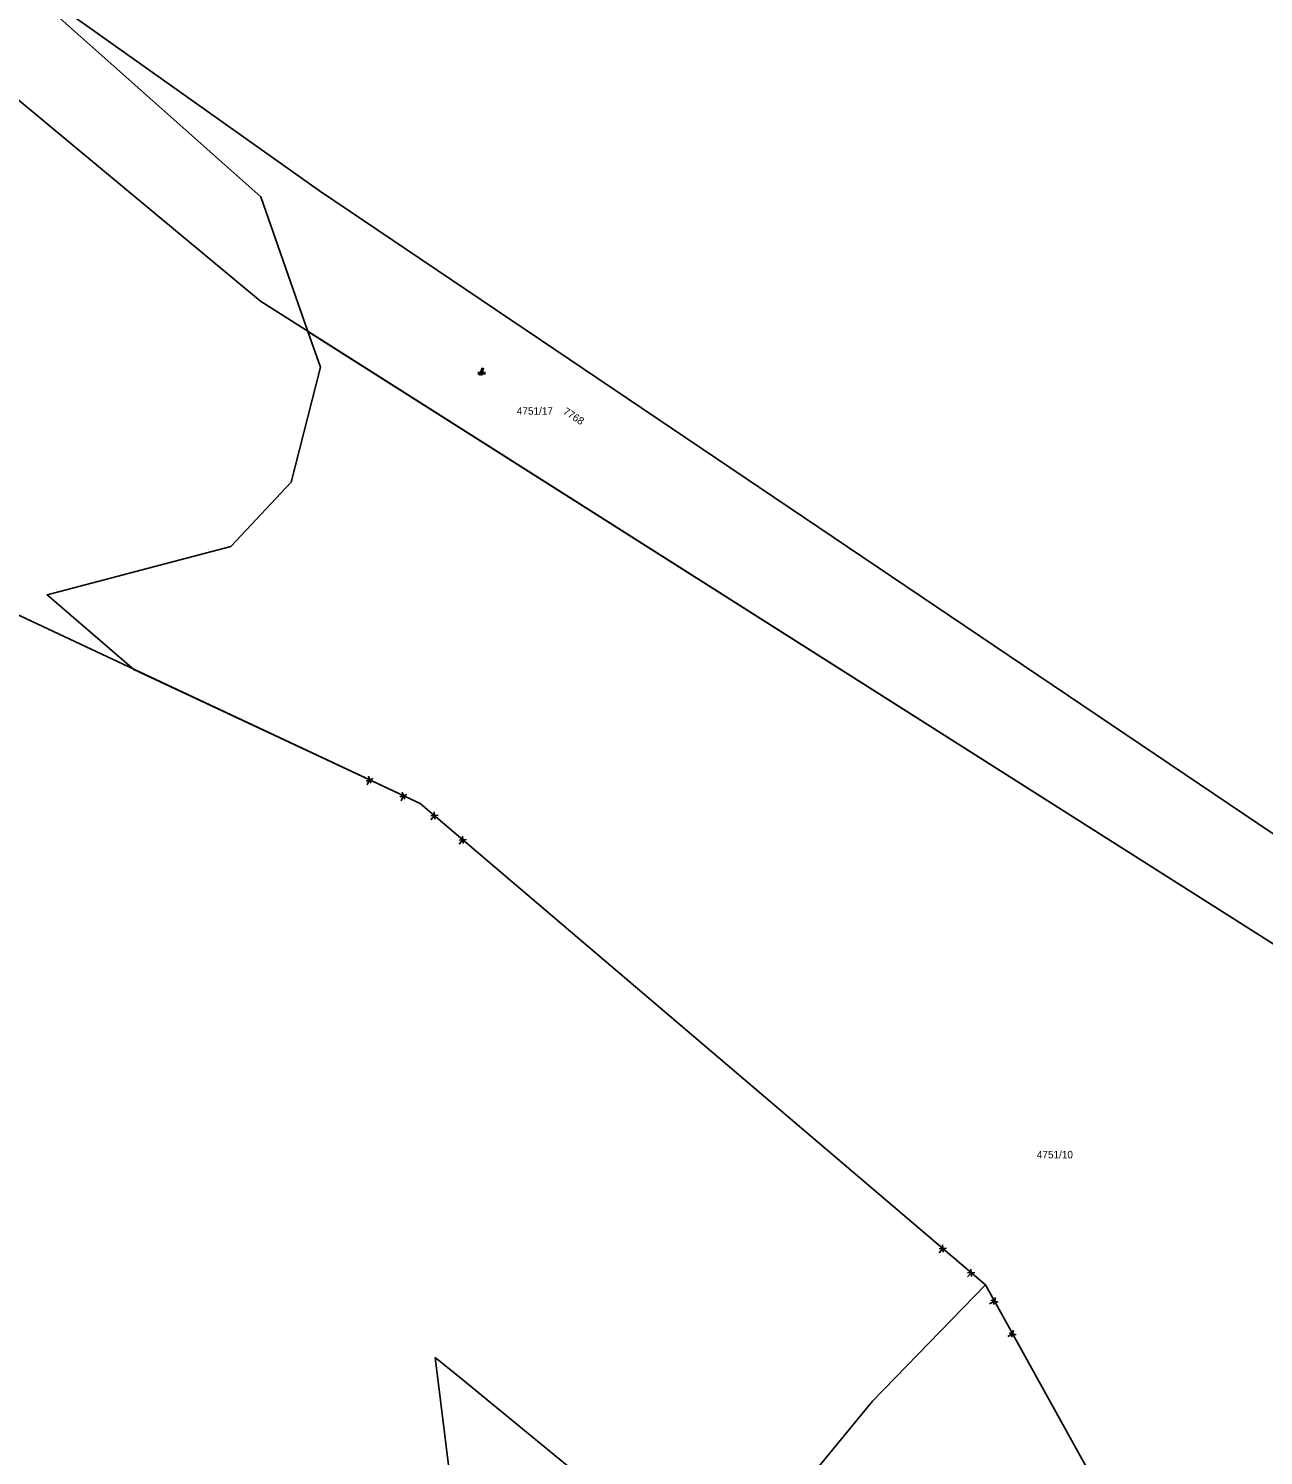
# Model space of a CAD drawing. Extents: x -439750 to -439180, y -1258684 to -1258308.
# Drawn here: x -439676.7 to -439610.6, y -1258440.1 to -1258363.6 of the extents above; entities that cross this region are included whole.
import ezdxf

# ---------------------------------------------------------------- set-up
doc = ezdxf.new("R2010")
doc.units = 0
doc.layers.add('KATASTER', color=7, linetype='Continuous')
doc.layers.add('UOV', color=7, linetype='Continuous')

# ---------------------------------------------------------------- blocks, each defined once
blk = doc.blocks.new('CESTA')
for p, q in [((-0.32, 0.8), (-1, 0.8)), ((-1, 0.4), (-0.46, 0.4)), ((0.1, 2), (-0.6, 0)), ((-0.1, 0), (0.5, 2)), ((0.02, 0.4), (1, 0.4)), ((1, 0.8), (0.14, 0.8))]:
    blk.add_line(p, q)
blk = doc.blocks.new('2072')
for p, q in [((-4.3, 0.7), (-5.7, -0.7)), ((-5.7, 0.7), (-4.3, -0.7)), ((-5, 0), (-5, -1.5)), ((4.3, 0.7), (5.7, -0.7)), ((5.7, 0.7), (4.3, -0.7)), ((5, 0), (5, -1.5))]:
    blk.add_line(p, q)

msp = doc.modelspace()

# ---------------------------------------------------------------- linework, layer by layer
at = {"layer": 'KATASTER'}
for points in [[(-439562.436, -1258308.807), (-439517.56, -1258326.72), (-439510.66, -1258363.93), (-439529.05, -1258372.98), (-439583.01, -1258405.44), (-439590.88, -1258409.26), (-439606.92, -1258408.85), (-439661.16, -1258372.28), (-439678.1, -1258360.24), (-439700.63, -1258331.393)], [(-439700.63, -1258331.393), (-439678.1, -1258360.24), (-439661.16, -1258372.28), (-439606.92, -1258408.85), (-439590.88, -1258409.26), (-439583.01, -1258405.44), (-439581.78, -1258408.62), (-439588.39, -1258414.26), (-439607.94, -1258413.98), (-439664.32, -1258378.2), (-439680.32, -1258364.89), (-439706.952, -1258332.427)], [(-439680.32, -1258364.89), (-439664.32, -1258378.2), (-439607.94, -1258413.98), (-439588.39, -1258414.26), (-439581.78, -1258408.62), (-439578.76, -1258414.75), (-439570.17, -1258432.21), (-439566.51, -1258439.64), (-439567.09, -1258440.4), (-439572.34, -1258446.7), (-439579.1, -1258452.12), (-439586.76, -1258455.52), (-439594.1, -1258457.31), (-439604.91, -1258457.14), (-439610.82, -1258457.46), (-439627.78, -1258463.49), (-439614.4, -1258450.89), (-439625.47, -1258430.92), (-439655.75, -1258405.12), (-439680.64, -1258393.46)], [(-439529.05, -1258372.98), (-439583.01, -1258405.44), (-439581.78, -1258408.62), (-439578.76, -1258414.75), (-439570.17, -1258432.21), (-439566.51, -1258439.64), (-439567.09, -1258440.4), (-439572.34, -1258446.7), (-439579.1, -1258452.12), (-439586.76, -1258455.52), (-439594.1, -1258457.31), (-439604.91, -1258457.14), (-439610.82, -1258457.46), (-439627.78, -1258463.49), (-439614.4, -1258450.89), (-439625.47, -1258430.92), (-439655.75, -1258405.12), (-439680.64, -1258393.46)], [(-439680.64, -1258393.46), (-439655.75, -1258405.12), (-439625.47, -1258430.92), (-439614.4, -1258450.89), (-439627.78, -1258463.49), (-439610.82, -1258457.46), (-439604.91, -1258457.14), (-439594.1, -1258457.31), (-439586.76, -1258455.52), (-439579.1, -1258452.12), (-439572.34, -1258446.7), (-439567.09, -1258440.4), (-439566.51, -1258439.64), (-439570.17, -1258432.21), (-439578.76, -1258414.75), (-439581.78, -1258408.62), (-439583.01, -1258405.44), (-439529.05, -1258372.98)]]:
    msp.add_lwpolyline(points, dxfattribs=at)
msp.add_lwpolyline([(-439654.95, -1258434.81), (-439653.48, -1258436.02), (-439639.58, -1258447.44), (-439637.04, -1258443.88), (-439631.52, -1258437.16), (-439625.47, -1258430.92), (-439614.4, -1258450.89), (-439627.78, -1258463.49), (-439649.29, -1258475.58), (-439651.22, -1258464.92)], close=True, dxfattribs=at)
at = {"layer": 'UOV'}
for points in [[(-439700.63, -1258331.393), (-439678.1, -1258360.24), (-439661.16, -1258372.28), (-439606.92, -1258408.85), (-439590.88, -1258409.26), (-439583.01, -1258405.44), (-439581.78, -1258408.62), (-439588.39, -1258414.26), (-439607.94, -1258413.98), (-439661.77, -1258379.82), (-439664.29, -1258372.6), (-439677.47, -1258360.86), (-439697.57, -1258343.86), (-439706.951, -1258332.426)], [(-439529.05, -1258372.98), (-439583.01, -1258405.44), (-439590.88, -1258409.26), (-439606.92, -1258408.85), (-439661.16, -1258372.28), (-439678.1, -1258360.24), (-439700.63, -1258331.393)], [(-439614.4, -1258450.89), (-439625.47, -1258430.92), (-439655.75, -1258405.12), (-439671.11, -1258397.93), (-439675.75, -1258393.93), (-439665.91, -1258391.35), (-439662.68, -1258387.9), (-439661.1, -1258381.73), (-439661.77, -1258379.82), (-439607.94, -1258413.98), (-439588.39, -1258414.26), (-439581.78, -1258408.62), (-439578.76, -1258414.74), (-439580.73, -1258416.42), (-439579.38, -1258423.01), (-439570.17, -1258432.21), (-439566.51, -1258439.64), (-439567.09, -1258440.4)]]:
    msp.add_lwpolyline(points, dxfattribs=at)

# ---------------------------------------------------------------- block references
at = {"layer": 'KATASTER', "xscale": 0.2, "yscale": 0.20000000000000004}
msp.add_blockref('CESTA', (-439652.46, -1258382.17), dxfattribs=at)
at = {"layer": 'KATASTER'}
for p, xscale, yscale, rotation in [((-439657.561, -1258404.272), 0.19999999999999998, 0.19999999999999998, -25.106169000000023), ((-439654.228, -1258406.417), 0.2, 0.20000000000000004, -40.40414199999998), ((-439626.992, -1258429.623), 0.2, 0.20000000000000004, -40.40414199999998), ((-439624.5, -1258432.669), 0.20000000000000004, 0.2, -60.97332699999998)]:
    msp.add_blockref('2072', p, dxfattribs=dict(at, xscale=xscale, yscale=yscale, rotation=rotation))

# ---------------------------------------------------------------- texts
msp.add_text('7768', height=0.4, rotation=326.872, dxfattribs=at).set_placement((-439648.137, -1258384.199))
at = {"layer": 'UOV'}
for s, p in [('4751/17', (-439650.578, -1258384.275)), ('4751/10', (-439622.714, -1258424.14))]:
    msp.add_text(s, height=0.4, dxfattribs=at).set_placement(p)

doc.saveas('drawing.dxf')
